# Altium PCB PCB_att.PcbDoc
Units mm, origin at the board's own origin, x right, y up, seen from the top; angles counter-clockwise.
Board outline 120.02 x 50 mm, 2 copper layers (Top Layer, Bottom Layer); 35 components, 64 nets, 213 pads, 26 vias.
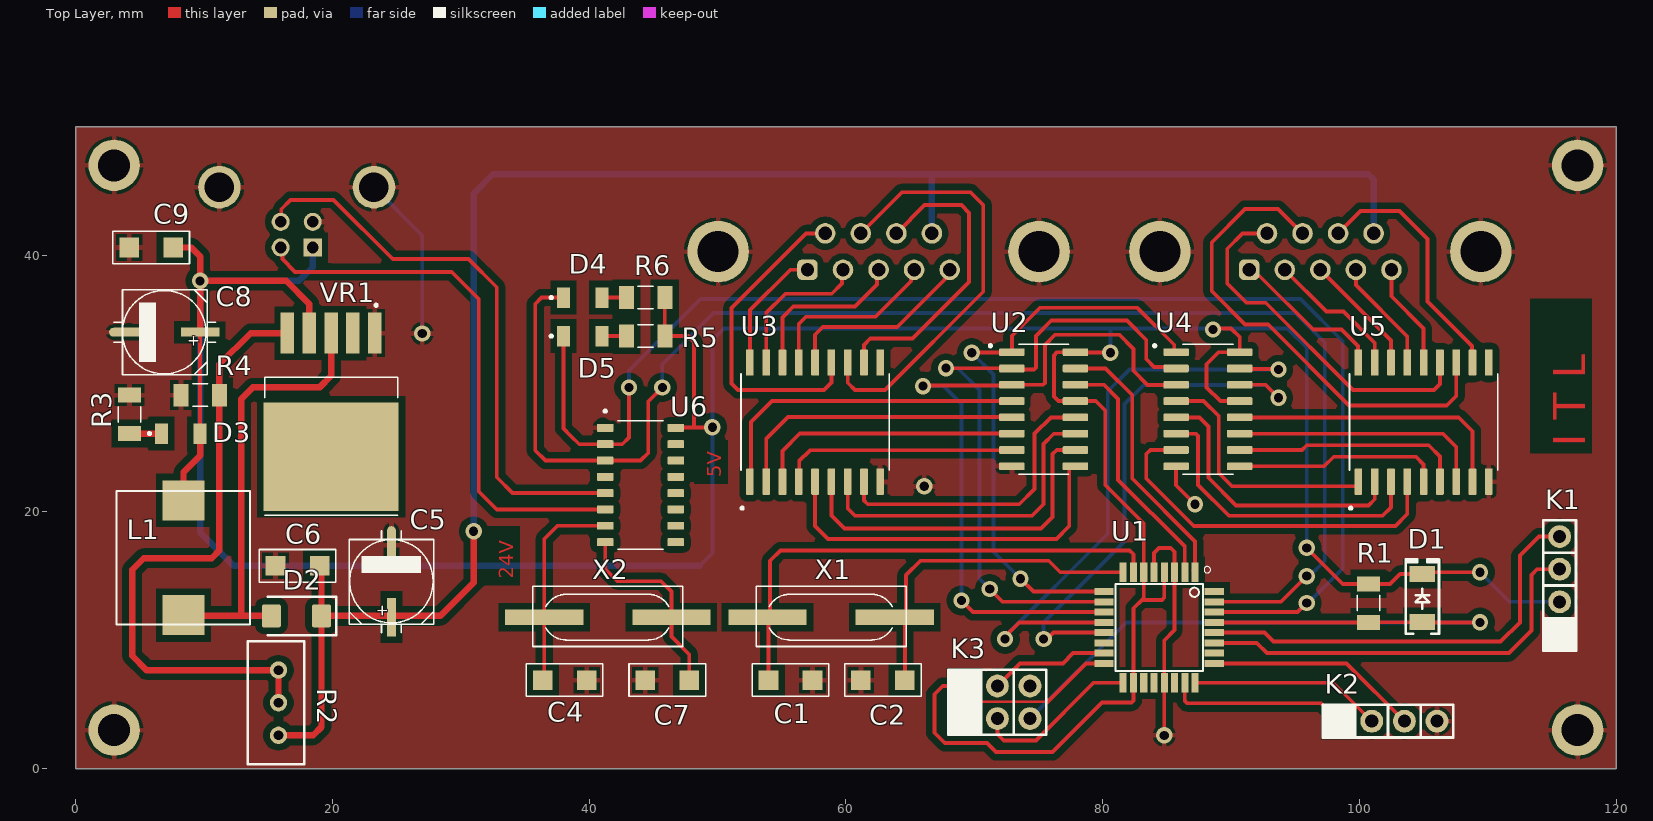
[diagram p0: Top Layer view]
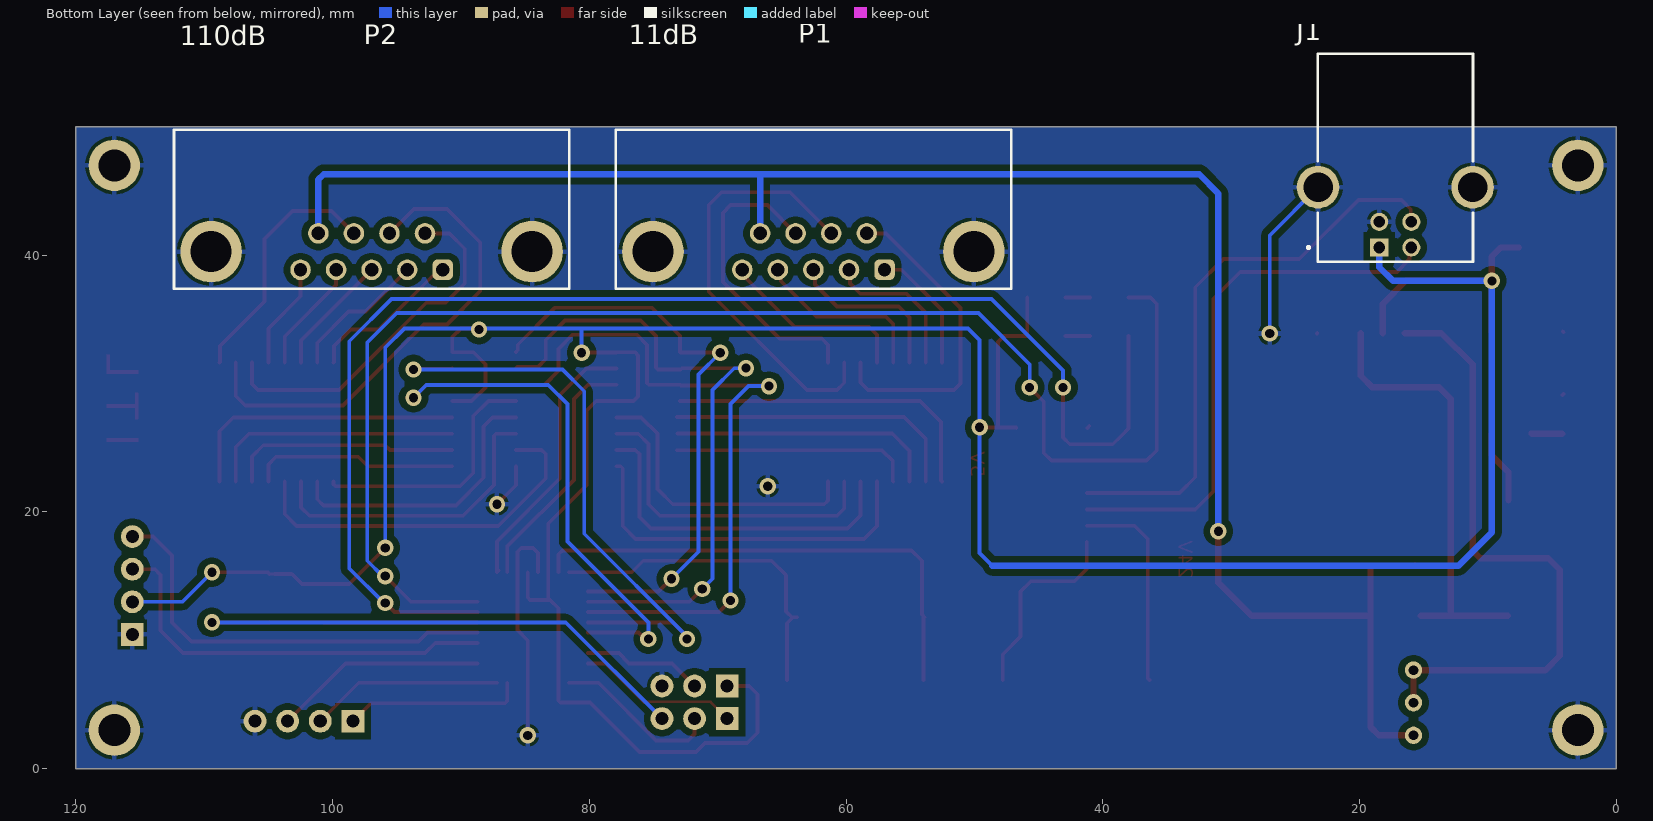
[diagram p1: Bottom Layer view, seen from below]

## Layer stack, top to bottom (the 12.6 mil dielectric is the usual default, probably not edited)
Top Solder: solder mask 0.0102, Solder Resist, Dk 3.5
Top Layer: signal copper 0.0356
Dielectric 1: dielectric 0.32, FR-4, Dk 4.8
Bottom Layer: signal copper 0.0356
Bottom Solder: solder mask 0.0102, Solder Resist, Dk 3.5

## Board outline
0,0 120.015,0 120.015,50 0,50

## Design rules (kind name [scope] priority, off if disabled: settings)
Clearance [All] p1: gap=0.5 ignorepadtopadclearanceinfootprint=FALSE
PolygonConnect [All] p1: connectstyle=Relief reliefconductorwidth=0.4 reliefentries=4 polygonreliefangle="90 Angle" airgapwidth=0.254
RoomDefinition Sch_att [InComponentClass('Sch_att')] p1: confinementstyle=ConfineIn formatcopy=TRUE lockcomponents=FALSE outline 121.2,1.4 140,1.4 140,35.6 121.2,35.6
RoutingVias [All] p1: holewidth=0.711 width=1.27 viastyle="Through Hole" minholewidth=0.711 minwidth=1.27 maxholewidth=0.711 maxwidth=1.27
SolderMaskExpansion [All] p1: expansion=0.102 istentingtop=FALSE
Width [All] p1: maxlimit=0.254 minlimit=0.254 preferedwidth=0.254
30 further rules are at their usual default settings.

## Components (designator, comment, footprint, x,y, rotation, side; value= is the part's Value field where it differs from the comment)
C1 "12pF" 1206C-GENERIC 57.4,6.9 r180 top
C2 "12pF" 1206C-GENERIC 61.171,6.9 r0 top
C4 "22pF" 1206C-GENERIC 39.8,6.9 r180 top
C5 "100u,35V" PANACAP-D-GENERIC 24.6,14.6 r90 top
C6 "50n" 1206C-GENERIC 15.571,15.8 r0 top
C7 "22pF" 1206C-GENERIC 44.371,6.9 r0 top
C8 "100u,35V" PANACAP-D-GENERIC 6.9,34 r180 top
C9 "50n" 1206C-GENERIC 4.171,40.6 r0 top
D1 "BAS83-GS08" "SOD-80 MiniMELF" 104.9,13.3 r90 top
D2 "Schottky-Diode" DO-214AC_SMA 17.2,11.9 r180 top
D3 "Red, 2V, 70°" WL-SMCW_1206_150120xx87000 8.2,26.1 r0 top
D4 "Blue, 3.2V, 70°" WL-SMCW_1206_150120xx87000 39.5,33.7 r0 top
D5 "Blue, 3.2V, 70°" WL-SMCW_1206_150120xx87000 39.5,36.7 r0 top
J1 "USB-B-S-X-X-TH" SAMTEC_USB-B-S-X-X-TH 17.22,45.3 r0 bottom
K1 "HEADER-1X4 display" HEADER-1X4 115.6,10.46 r180 top
K2 "HEADER-1X4 encoder" HEADER-1X4 98.42,3.7 r90 top
K3 "HEADER-2X3" HEADER-2X3 69.26,3.9 r90 top
L1 "470" IHLP4040DZER220M5A 8.4,16.429 r270 top
P1 "11dB" 618009231221 62.545,43.58 r0 bottom
P2 "110dB" 618009231221 96.955,43.58 r0 bottom
R1 "10k" RESC3216X75N 100.7,12.9 r270 top
R2 "10k" "BOURNS TRIMPOT 3296W" 15.8,5.14 r270 top value="100 Ohms"
R3 "5k" RESC3216X75N 4.2,27.6 r270 top
R4 "330" RESC3216X75N 9.7,29.1 r0 top
R5 "5k" RESC3216X75N 44.4,33.7 r180 top
R6 "5k" RESC3216X75N 44.4,36.7 r180 top
U1 "ATMEGA328-AU" QFP80P900X900X120-32N 84.4,11 r270 top
U2 "SN74HC259DT" SOIC127P600X175-16N 75.4,28 r0 top
U3 "ULN2803ADW" SOIC127P1030X265-18N 57.6,27 r90 top
U4 "SN74HC259DT" SOIC127P600X175-16N 88.2,28 r0 top
U5 "ULN2803ADW" SOIC127P1030X265-18N 105,27 r90 top
U6 "CH340G" SOIC127P600X180-16N 44,22.1 r0 top
VR1 "XL6009" DPAK170P1435X465-6N 19.9,27.8 r270 top
X1 "16MHz" XTAL-RU49/4 53.894,11.8 r0 top
X2 "12MHz" XTAL-RU49/4 36.5,11.8 r0 top

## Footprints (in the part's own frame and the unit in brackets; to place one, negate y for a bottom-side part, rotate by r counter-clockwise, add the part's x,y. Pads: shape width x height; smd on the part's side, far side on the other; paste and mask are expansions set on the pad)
1206C-GENERIC [mil]
  rect 60x60 smd: 1(0,0) 2(135,0)
  silkscreen extent -50,-50 185,50, body extent -8,-29 147,29, height 46
618009231221 [mm] "9 pins, right angled, 8.08mm, with hex screw"
  rrect50% 1.6x1.6 hole 1.04: 1(-5.54,4.72)
  round 1.6 hole 1.04: 2(-2.77,4.72) 3(0,4.72) 4(2.77,4.72) 5(5.54,4.72) 6(-4.155,1.88) 7(-1.385,1.88) 8(1.385,1.88) 9(4.155,1.88)
  round 4.8 hole 3.2: M1(-12.5,3.3) M2(12.5,3.3)
  silkscreen extent -15.4,-6.2 15.4,6.2, body extent -15.4,-12.2 15.4,6.2, height 12.57
"BOURNS TRIMPOT 3296W" [mm] "3296 - 3/8 ? Square Trimpot® Trimming Potentiometer"
  round 1.35 hole 0.75: 1(-2.54,0) 2(0,0) 3(2.54,0)
  silkscreen extent -4.8,-2.4 4.8,2, body extent -4.76,-2.41 4.76,2.41, height 11.56
DO-214AC_SMA [mm]
  rrect25% 1.5x1.8 smd: A(1.95,0) K(-1.95,0)
  silkscreen extent -3.1,-1.5 2.25,1.5, body extent -2.53,-1.35 2.52,1.35, height 2.17
DPAK170P1435X465-6N [mm]
  rect 3.21x1.05 smd: 1(-6.13,3.4) 2(-6.13,1.7) 3(-6.13,0) 4(-6.13,-1.7) 5(-6.13,-3.4)
  rect 8.46x10.53 smd paste-6: 6(3.5,0)
  silkscreen extent -8.4,-5.18 8.05,5.18, body extent -7.17,-5.08 7.17,5.08, height 4.65
HEADER-1X4 [mil]
  rect 70x70 hole 40: 1(0,0)
  round 70 hole 40: 2(0,-100) 3(0,-200) 4(0,-300)
  silkscreen extent -51,-350 50,50, body extent -50,-350 50,50, height 470
HEADER-2X3 [mil]
  rect 70x70 hole 40: 1(0,0) 2(100,0)
  round 70 hole 40: 3(0,-100) 4(100,-100) 5(0,-200) 6(100,-200)
  silkscreen extent -50,-250 150,50, body extent -50,-250 150,50, height 470
IHLP4040DZER220M5A [mm]
  rect 3.124x3.251 smd: 1(-4.47,0) 2(4.471,0)
  silkscreen extent -5.2,-5.2 5.2,5.2
PANACAP-D-GENERIC [mm]
  rect 3x0.7 smd: +(-2.794,0)
  oval 3x0.7 smd: -(2.794,0)
  silkscreen extent -4,-3.3 3.92,3.3, body extent -3.5,-3.3 3.5,3.3, height 5.4
QFP80P900X900X120-32N [mm]
  rect 1.5x0.55 smd: 1(-4.3,2.8) 2(-4.3,2) 3(-4.3,1.2) 4(-4.3,0.4) 5(-4.3,-0.4) 6(-4.3,-1.2) 7(-4.3,-2) 8(-4.3,-2.8) 17(4.3,-2.8) 18(4.3,-2) 19(4.3,-1.2) 20(4.3,-0.4) 21(4.3,0.4) 22(4.3,1.2) 23(4.3,2) 24(4.3,2.8)
  rect 0.55x1.5 smd: 9(-2.8,-4.3) 10(-2,-4.3) 11(-1.2,-4.3) 12(-0.4,-4.3) 13(0.4,-4.3) 14(1.2,-4.3) 15(2,-4.3) 16(2.8,-4.3) 25(2.8,4.3) 26(2,4.3) 27(1.2,4.3) 28(0.4,4.3) 29(-0.4,4.3) 30(-1.2,4.3) 31(-2,4.3) 32(-2.8,4.3)
  silkscreen extent -4.75,-3.4 3.4,4, body extent -4.5,-4.5 4.5,4.5, height 0.53
RESC3216X75N [mm]
  rect 1.17x1.77 smd: 1(-1.494,0) 2(1.494,0)
  silkscreen extent -0.59,-0.88 0.59,0.88
SAMTEC_USB-B-S-X-X-TH [mm]
  rect 1.408x1.408 / inner round 1.408 / far side rect 1.408x1.408 hole 0.9: 1(1.25,4.7)
  round 1.408 hole 0.9: 2(-1.25,4.7) 3(-1.25,2.7) 4(1.25,2.7)
  round 3.316 hole 2.3: S1(-6.02,0) S2(6.02,0)
  silkscreen extent -6.05,-10.4 6.85,5.8
"SOD-80 MiniMELF" [mm] "Molded Diode, 2-Leads, Body 3.40x1.50mm, IPC Medium Density"
  rect 1.25x2 smd: 1(-1.875,0) 2(1.875,0)
  silkscreen extent -2.8,-1.3 2.99,1.3, body extent -1.7,-0.75 1.7,0.75, height 1.5
SOIC127P600X175-16N [mm]
  rrect25% 1.97x0.6 smd: 1(-2.475,4.445) 2(-2.475,3.175) 3(-2.475,1.905) 4(-2.475,0.635) 5(-2.475,-0.635) 6(-2.475,-1.905) 7(-2.475,-3.175) 8(-2.475,-4.445) 9(2.475,-4.445) 10(2.475,-3.175) 11(2.475,-1.905) 12(2.475,-0.635) 13(2.475,0.635) 14(2.475,1.905) 15(2.475,3.175) 16(2.475,4.445)
  silkscreen extent -4.24,-5.06 1.95,5.06
SOIC127P600X180-16N [mm]
  rrect25% 1.31x0.62 smd: 1(-2.75,4.445) 2(-2.75,3.175) 3(-2.75,1.905) 4(-2.75,0.635) 5(-2.75,-0.635) 6(-2.75,-1.905) 7(-2.75,-3.175) 8(-2.75,-4.445) 9(2.75,-4.445) 10(2.75,-3.175) 11(2.75,-1.905) 12(2.75,-0.635) 13(2.75,0.635) 14(2.75,1.905) 15(2.75,3.175) 16(2.75,4.445)
  silkscreen extent -2.85,-5 1.78,5.85, body extent -3,-5 3,5, height 1.8
SOIC127P1030X265-18N [mm]
  rrect25% 2.06x0.6 smd: 1(-4.64,5.08) 2(-4.64,3.81) 3(-4.64,2.54) 4(-4.64,1.27) 5(-4.64,0) 6(-4.64,-1.27) 7(-4.64,-2.54) 8(-4.64,-3.81) 9(-4.64,-5.08) 10(4.64,-5.08) 11(4.64,-3.81) 12(4.64,-2.54) 13(4.64,-1.27) 14(4.64,0) 15(4.64,1.27) 16(4.64,2.54) 17(4.64,3.81) 18(4.64,5.08)
  silkscreen extent -6.8,-5.78 3.75,5.78, body extent -5.15,-5.77 5.15,5.77, height 2.65
WL-SMCW_1206_150120xx87000 [mm] "LED, SMT, 2-leads, body 3.20x1.60mm"
  rect 1x1.6 smd: 1(-1.5,0) 2(1.5,0)
  silkscreen extent -2.55,-0.1 -2.35,0.1, body extent -1.6,-0.8 1.6,0.8, height 1.1
XTAL-RU49/4 [mil]
  rect 240x47.24 smd: 1(0,0) 2(390,0)
  silkscreen extent -35,-90 425,95, body extent -78,-90 468,95, height 120

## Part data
C1 C2 C4 C6 C7 C9: library part 1206C-10U-35V-X7R, "GENERIC CAPACITOR NON POLARISED 1206", Manufacturer="Taiyo Yuden", Manufacturer Part Number=GMK316F106ZL-T, Supplier Part Number 1=587-1352-2-ND
C5 C8: library part PANACAP-100UF-16V-FK, "GENERIC CAPACITOR POLARISED", Supplier Part Number 1=PCE3783TR-ND
D1: "DIODE SCHOTTKY 60V 30MA SOD80", Capacitance @ Vr, F="1.6pF @ 1V, 1MHz", Current - Average Rectified (Io)="30mA (DC)", Current - Reverse Leakage @ Vr="200nA @ 60V", Manufacturer="Vishay Semiconductor Diodes Division", Operating Temperature - Junction="125°C (Max)", Package / Case="DO-213AC, MINI-MELF, SOD-80", Supplier Device Package="SOD-80 MiniMELF", Supplier Part Number 1=BAS83-GS08GICT-ND, Voltage - DC Reverse (Vr) (Max)=60V, Voltage - Forward (Vf) (Max) @ If="1V @ 15mA"
D3: library part 150120RS87000, "WL-SMCW Mono-color Chip LED Waterclear, size 1206, Red, 2V, 70°", Case/Size Code=1206, Emitting Color=Red, Forward Voltage=2V, Manufacturer="Wurth Elektronik", Operating Temperature Max=85°C, Operating Temperature Min=-40°C
D4 D5: library part 150120BS87000, "WL-SMCW Mono-color Chip LED Waterclear, size 1206, Blue, 3.2V, 70°", Case/Size Code=1206, Emitting Color=Blue, Forward Voltage=3.2V, Manufacturer="Wurth Elektronik", Operating Temperature Max=85°C, Operating Temperature Min=-40°C
J1: "USB-B (USB TYPE-B) USB 2.0 Receptacle Connector 4 Position Through Hole, Right Angle", Package=None
K1 K2: library part HEADER-1X4, Supplier Part Number 1=S1011E-36-ND
L1: library part IHLP4040DZER220M5A, "22 ÂµH Shielded Molded Inductor 4.1 A 75.44mOhm Max Nonstandard", Package="Nonstandard Vishay Dale"
P1 P2: library part 618009231221, "WR-DSUB 8.08mm Male PCB Connector with Hex Screw, Angled, 9p", Contact Resistance=30mOhm, Manufacturer="Wurth Elektronik", Operating Temperature Max=105°C, Operating Temperature Min=-55°C, Rated Current=3A, Withstanding Voltage=100VAC, Working Voltage=125VAC
R1: library part CR1206-FX-4701ELF, "RES 10K OHM 1/4W 1% 1206 SMD", Package=None
R2: library part 3296W-1-101RLF, "TRIMMER 100 OHM 0.5W PC PIN TOP", Manufacturer="Bourns Inc.", Power (Watts)="0.5W, 1/2W", Resistance="100 Ohms", Resistive Material=Cermet, Supplier Part Number 1=118-3296W-1-101RLFCT-ND, Temperature Coefficient=±100ppm/°C, Tolerance=±10%
R3 R4 R5 R6: library part CR1206-FX-4701ELF, "RES 5K OHM 1/4W 1% 1206 SMD", Package=None
U1: "AVR AVRÂ® ATmega Microcontroller IC 8-Bit 20MHz 32KB (16K x 16) FLASH 32-TQFP (7x7)", Package="TQFP-32 Microchip"
U2 U4: Package=None
U3 U5: "50-V, 8-ch darlington array", Package="SOIC-18 Texas Instruments"
U6: "USB Interface Integrated Circuit", Package=None
VR1: "The XL6009 regulator is a wide input range, current mode, DC/DC converter which is capable of generating either positive or negative output voltages.", Package="TO-263-5L XLSEMI"
X1 X2: library part CRYSTAL-GENERIC, "GENERIC CRYSTAL"

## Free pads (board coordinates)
  round 4 hole 2.5: ""(3,3) ""(3,47) ""(117,3) ""(117,47)

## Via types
v1: diameter 1.27, hole 0.711, Top Layer to Bottom Layer, 26 vias

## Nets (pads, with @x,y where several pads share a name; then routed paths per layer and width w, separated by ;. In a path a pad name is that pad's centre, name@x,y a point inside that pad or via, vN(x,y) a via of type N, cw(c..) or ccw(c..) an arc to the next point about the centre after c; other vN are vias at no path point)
1-1C: P1.1 U3.18 | length 9.9
  Top Layer w0.3: U3.18 52.52,35.72 55.66,38.86 P1.1
1-2C: P1.2 U3.17 | length 11.8
  Top Layer w0.3: U3.17 53.79,35.49 55.3,37 58.9,37 59.686,37.786 59.686,38.771 P1.2
1-3C: P1.3 U3.16 | length 13.1
  Top Layer w0.3: U3.16 55.06,35.16 55.9,36 60.7,36 62.419,37.719 62.419,38.734 P1.3
1-4C: P1.4 U3.15 | length 14.1
  Top Layer w0.3: U3.15 56.33,34.63 56.9,35.2 62.3,35.2 65.066,37.966 65.066,38.611 P1.4
1-5C: P1.5 U3.14 | length 15
  Top Layer w0.3: U3.14 57.6,33.8 58.2,34.4 64,34.4 67.689,38.089 67.689,38.112 68.085,38.508 P1.5
1-6C: P1.6 U3.13 | length 25.4
  Top Layer w0.3: P1.6 56.9,41.7 51.1,35.9 51.1,30 51.6,29.5 58.3,29.5 58.87,30.07 U3.13
1-7C: P1.7 U3.12 | length 33.6
  Top Layer w0.3: U3.12 60.14,30.06 60.7,29.5 63.049,29.5 70.7,37.151 70.7,43.9 69.7,44.9 64.36,44.9 P1.7
1-8C: P1.8 U3.11 | length 23.8
  Top Layer w0.3: U3.11 61.41,33.01 61.9,33.5 65.2,33.5 69.6,37.9 69.6,43.3 69,43.9 66.13,43.9 P1.8
2-1C: P2.1 U5.18 | length 12.2
  Top Layer w0.3: P2.1 91.911,38.364 92.236,38.364 96.4,34.2 98.6,34.2 99.879,32.921 99.879,31.681 U5.18
2-2C: P2.2 U5.17 | length 10.9
  Top Layer w0.3: P2.2 97.445,35.6 98.763,35.6 101.19,33.173 U5.17
2-3C: P2.3 U5.16 | length 9.5
  Top Layer w0.3: P2.3 102.46,33.355 U5.16
2-4C: P2.4 U5.15 | length 8.9
  Top Layer w0.3: P2.4 99.725,37.675 103.73,33.67 U5.15
2-5C: P2.5 U5.14 | length 8.3
  Top Layer w0.3: P2.5 102.495,36.805 105,34.3 U5.14
2-6C: P2.6 U5.13 | length 28.2
  Top Layer w0.3: P2.6 90.9,41.7 89.7,40.5 89.7,37.8 91.2,36.3 92.7,36.3 99.5,29.5 105.8,29.5 106.27,29.97 U5.13
2-7C: P2.7 U5.12 | length 38.4
  Top Layer w0.3: P2.7 93.67,43.6 91.1,43.6 88.5,41 88.5,37.2 91.1,34.6 92.9,34.6 99.2,28.3 106.8,28.3 107.54,29.04 U5.12
2-8C: P2.8 U5.11 | length 19.7
  Top Layer w0.3: P2.8 100.084,43.444 103.119,43.444 105.31,41.254 105.31,36.39 108.774,32.926 108.774,31.676 U5.11
24V: C5.+ C6.2 D2.K P1.9 P2.9 R2.3 | length 139.3
  Top Layer w0.3: C6.2 C6.2@19.15,15.65 ; C5.+@24.506,11.9 C5.+ C5.+@24.694,11.9
  Top Layer w0.5: R2.3 18.5,2.6 19.15,3.25 D2.K ; C6.2@19.15,15.65 D2.K ; C5.+@24.506,11.9 D2.K ; C5.+@24.694,11.9 28.4,11.9 31,14.5 v1(31,18.5)
  Bottom Layer w0.3: 66.7,46.2 66.8,46.3 66.7,46.3
  Bottom Layer w0.5: v1(31,18.5) 31,44.8 32.5,46.3 66.7,46.3 ; P1.9 66.7,46.2 ; 66.8,46.3 100.7,46.3 101.11,45.89 P2.9
CLR1: U1.1 U2.15 | length 21.2
  Top Layer w0.3: U2.15 80.225,31.175 82.3,29.1 82.3,22.6 87.2,17.7 U1.1@87.2,15.444 ; U1.1@87.056,15.444 U1.1
CLR2: U1.12 U4.15 | length 47.6
  Top Layer w0.3: v1@72.4,10.3 73.5,11.4 U1.12 ; U4.15 90.713,31.137 93.663,31.137 v1(93.7,31.1)
  Bottom Layer w0.3: v1@72.4,10.3 80.4,18.3 80.4,29.4 82.1,31.1 v1(93.7,31.1)
  other v1: 72.4,10.1
D+: J1.3 U6.5 | length 44.7
  Top Layer w0.3: J1.3 16.021,42.651 16.021,43.578 16.743,44.3 20.1,44.3 24.7,39.7 30.6,39.7 32.8,37.5 32.8,22.7 34.035,21.465 U6.5
D-: J1.2 U6.6 | length 43
  Top Layer w0.3: J1.2 16.101,40.469 16.101,39.699 17.1,38.7 29.3,38.7 31.405,36.595 31.405,21.595 32.805,20.195 U6.6
EN1: U1.2 U2.14 | length 19.4
  Top Layer w0.3: U2.14 80.095,29.905 81.2,28.8 81.2,22.5 86.4,17.3 U1.2
EN2: U1.13 U4.14 | length 42.8
  Top Layer w0.3: v1(75.4,10.1) 75.675,10.1 76.175,10.6 U1.13 ; U4.14 92.695,29.905 v1(93.7,28.9) v1@94.2,28.9
  Bottom Layer w0.3: v1(75.4,10.1) 75.4,11.4 81.7,17.7 81.7,28.4 83.2,29.9 92.7,29.9 v1(93.7,28.9)
enc1: K2.1 U1.23 | length 14.1
  Top Layer w0.3: U1.23 86.4,5.276 86.576,5.1 97.02,5.1 K2.1
enc2: K2.2 U1.24 | length 15
  Top Layer w0.3: U1.24 97.96,6.7 K2.2
enc3: K2.3 U1.25 | length 16.7
  Top Layer w0.3: U1.25 99,8.2 K2.3
GND: C1.1 C2.1 C4.1 C5.- C6.1 C7.1 C8.- C9.1 J1.4 J1.S1 J1.S2 K1.1 K2.4 K3.6 P1.M1 P1.M2 P2.M1 P2.M2 pad. R3.1 R4.1 U1.3 U1.5 U1.21 U2.8 U3.9 U4.8 U5.9 U6.1 VR1.1 | length 37.6
  Top Layer w0.3: pad.@3,3 pad.@3,3.167 ; pad.@3,46.833 3,47 pad.@4.014,47 ; R3.1@4.106,29.188 R3.1 R3.1@4.206,29.1 ; C8.- C8.-@4.171,34.065 ; C6.1 C6.1@15.694,15.923 ; VR1.1 VR1.1@23.33,33.9 ; U6.1@41.055,26.694 U6.1@41.204,26.545 ; U1.5 84,16.8 84.4,17.2 85.3,17.2 85.6,16.9 U1.3 85.6,10.8 84.8,10 U1.21 v1(84.8,2.6) ; U4.8 85.725,22.075 v1(87.2,20.6) ; pad.@115.986,47 pad.@117,47
  Bottom Layer w0.3: J1.S2 27,41.54 v1(27,33.9)
  other v1: 66.1,22
MISO: K3.1 U1.16 | length 12.6
  Top Layer w0.2: K3.1 70.56,5.2 75.7,5.2
  Top Layer w0.3: 75.7,5.2 78.7,8.2 U1.16
MOSI: K3.4 U1.15 | length 9.4
  Top Layer w0.3: K3.4 73.56,8.2 76.9,8.2 77.7,9 U1.15
NetC1_2: C1.2 U1.7 X1.1 | length 39.5
  Top Layer w0.3: X1.1 54.1,12.006 54.1,16.2 54.9,17 82.1,17 82.4,16.7 U1.7 ; C1.2 X1.1@53.971,11.8
NetC2_2: C2.2 U1.8 X1.2 | length 26.7
  Top Layer w0.3: X1.2 X1.2@64.127,11.8 ; C2.2 64.6,11.327 X1.2@64.127,11.8 ; U1.8 78.1,15.3 76.7,15.3 75.8,16.2 65.8,16.2 64.674,15.074 64.674,12.25 64.224,11.8 X1.2@64.127,11.8
NetC4_2: C4.2 U6.7 X2.1 | length 16.2
  Top Layer w0.3: C4.2 36.5,7.029 X2.1 36.5,17.9 37.525,18.925 U6.7
NetC7_2: C7.2 U6.8 X2.2 | length 15.5
  Top Layer w0.3: U6.8 41.25,15.55 42.2,14.6 45.6,14.6 46.406,13.794 X2.2 46.406,10.294 47.8,8.9 C7.2
NetD2_A: D2.A L1.2 VR1.3 | length 34.8
  Top Layer w0.3: L1.2 L1.2@8.459,11.9
  Top Layer w0.5: L1.2@8.459,11.9 12.9,11.9 ; D2.A 12.9,11.9 ; VR1.3 19.9,30.6 19,29.7 13.8,29.7 12.9,28.8 12.9,11.9
NetD3_1: D3.1 R3.2 | length 2.5
  Top Layer w0.3: D3.1@6.606,26.106 D3.1@6.7,26.2
  Top Layer w0.5: R3.2 D3.1@6.606,26.106
NetD4_2: D4.2 R5.2 | length 1.9
  Top Layer w0.3: D4.2 R5.2
NetD5_2: D5.2 R6.2 | length 1.9
  Top Layer w0.3: D5.2 R6.2
NetR2_1: R2.1 R2.2 R4.2 VR1.5 | length 49.3
  Top Layer w0.5: R2.2 R2.1 5.52,7.68 4.4,8.8 4.4,15.5 5.3,16.4 10.6,16.4 11.194,16.994 R4.2 11.194,31.494 13.63,33.93 VR1.5
NetU2_4: U2.4 U3.1 | length 25.7
  Top Layer w0.3: U3.1 52.6,22.44 52.6,27 54.235,28.635 U2.4
NetU2_5: U2.5 U3.2 | length 23.4
  Top Layer w0.3: U3.2 53.79,25.69 55.5,27.4 U2.5@73.17,27.4
NetU2_6: U2.6 U3.3 | length 21.1
  Top Layer w0.3: U3.3 55.06,24.76 56.4,26.1 U2.6@73.155,26.1
NetU2_7: U2.7 U3.4 | length 18.8
  Top Layer w0.3: U3.4 56.36,22.39 56.36,23.96 57.2,24.8 U2.7@73.168,24.8
NetU2_9: U2.9 U3.5 | length 29.1
  Top Layer w0.3: U3.5 57.6,18.9 58.6,17.9 76.4,17.9 77.4,18.9 77.4,23.405 77.55,23.555 U2.9
NetU2_10: U2.10 U3.6 | length 27.5
  Top Layer w0.3: U3.6 58.87,19.73 59.9,18.7 75.2,18.7 76.1,19.6 76.1,24.5 76.425,24.825 U2.10
NetU2_11: U2.11 U3.7 | length 25.5
  Top Layer w0.3: U3.7 60.14,20.26 60.7,19.7 74.5,19.7 75.4,20.6 75.4,25.3 76.195,26.095 U2.11
NetU2_12: U2.12 U3.8 | length 23.4
  Top Layer w0.3: U3.8 61.41,20.89 61.7,20.6 73.5,20.6 74.7,21.8 74.7,26.1 75.965,27.365 U2.12
NetU4_4: U4.4 U5.1 | length 19.8
  Top Layer w0.3: U4.4 87.865,28.635 89.04,27.46 89.04,23.03 90.07,22 99.77,22 99.92,22.15 U5.1
NetU4_5: U4.5 U5.2 | length 22.2
  Top Layer w0.3: U4.5 87.535,27.365 88.24,26.66 88.24,22.66 90.4,20.5 100.7,20.5 101.19,20.99 U5.2
NetU4_6: U4.6 U5.3 | length 23.9
  Top Layer w0.3: U4.6 87.264,26.095 87.44,25.919 87.44,22.097 89.837,19.7 101.8,19.7 102.46,20.36 U5.3
NetU4_7: U4.7 U5.4 | length 29.1
  Top Layer w0.3: U4.7 83.725,24.825 83.4,24.5 83.4,22.6 87.1,18.9 102.8,18.9 103.73,19.83 U5.4
NetU4_9: U4.9 U5.5 | length 16.2
  Top Layer w0.3: U4.9 97.255,23.555 98,24.3 104.4,24.3 105,23.7 U5.5
NetU4_10: U4.10 U5.6 | length 18.1
  Top Layer w0.3: U4.10 95.525,24.825 95.9,25.2 105.4,25.2 106.27,24.33 U5.6
NetU4_11: U4.11 U5.7 | length 20
  Top Layer w0.3: U4.11 106.505,26.095 107.54,25.06 U5.7
NetU4_12: U4.12 U5.8 | length 22.5
  Top Layer w0.3: U4.12 107.735,27.365 108.81,26.29 U5.8
RST: D1.1 K3.5 R1.2 U1.29 | length 58.5
  Top Layer w0.3: U1.29 R1.2@100.7,11.4 ; R1.2 104.881,11.406 D1.1 104.925,11.4 v1@109.2,11.4
  Bottom Layer w0.3: K3.5 81.84,11.4 v1@109.2,11.4
  other v1: 109.4,11.4
RXD: D5.1 U1.31 U6.3 | length 111.7
  Top Layer w0.3: D5.1 36.3,36.7 35.8,36.2 35.8,24.8 36.595,24.005 U6.3 44.005,24.005 44.6,24.6 44.6,28.6 v1(45.7,29.7) ; U1.31 93.9,13 v1(95.9,15)
  Bottom Layer w0.3: v1(45.7,29.7) 45.7,31.5 49.7,35.5 95,35.5 97.3,33.2 97.3,16.2 96.1,15 v1(95.9,15)
S0: U1.9 U2.1 U4.1 | length 45.9
  Top Layer w0.3: v1(69.8,32.4) 69.823,32.423 72.902,32.423 U2.1 72.925,33.725 75.1,35.9 82.7,35.9 85.581,33.019 85.581,32.595 85.725,32.451 U4.1 ; v1(73.6,14.8) 74.6,13.8 U1.9
  Bottom Layer w0.3: v1(69.8,32.4) 71.5,30.7 71.5,16.9 v1(73.6,14.8)
S1: U1.10 U2.2 U4.2 | length 51.8
  Top Layer w0.3: v1(67.8,31.2) 67.812,31.188 72.806,31.188 72.893,31.1 74.651,31.1 74.8,31.249 74.8,33.7 76,34.9 81.9,34.9 83.4,33.4 83.4,31.9 84,31.3 85.6,31.3 U4.2 ; v1(71.2,14) 72.2,13 U1.10
  Bottom Layer w0.3: v1(67.8,31.2) 67.809,31.191 68.709,31.191 70.4,29.5 70.4,14.8 v1(71.2,14)
S2: U1.11 U2.3 U4.3 | length 56.1
  Top Layer w0.3: v1(66,29.8) 66.053,29.853 72.872,29.853 U2.3 75.351,29.905 75.5,30.054 75.5,33 76.3,33.8 81.3,33.8 82.4,32.7 82.4,31 83.5,29.9 85.72,29.9 U4.3 ; v1(69,13.1) 69.9,12.2 U1.11
  Bottom Layer w0.3: v1(66,29.8) 67.6,29.8 69,28.4 v1(69,13.1)
SCK: K3.3 U1.17 | length 13.1
  Top Layer w0.3: K3.3 71.8,2.7 72.3,2.2 74.8,2.2 79.3,6.7 U1.17
SCL: K1.4 U1.28 | length 33.6
  Top Layer w0.3: U1.28 92.6,10.6 93.3,9.9 111,9.9 112.5,11.4 112.5,16.6 113.98,18.08 K1.4
SDA: K1.3 U1.27 | length 32.5
  Top Layer w0.3: U1.27 92,9.8 92.8,9 111.64,9 113.4,10.76 113.4,15.1 113.84,15.54 K1.3
TXD: D4.1 U1.30 U6.2 | length 106.6
  Top Layer w0.3: D4.1 38,26.5 38.6,25.9 39.225,25.275 U6.2 42.575,25.275 43.1,25.8 v1(43.1,29.7) ; U1.30 95.166,12.2 95.866,12.9 v1@96,12.9
  Bottom Layer w0.3: v1(43.1,29.7) 43.1,31.016 48.684,36.6 95.4,36.6 98.7,33.3 98.7,15.6 v1@96,12.9
  other v1: 95.9,12.9
VCC: C8.+ C9.2 D1.2 D3.2 J1.1 K1.2 K3.2 L1.1 R1.1 R5.1 R6.1 U1.4 U1.6 U1.18 U2.13 U2.16 U4.13 U4.16 U6.16 VR1.4 | length 298.6
  Top Layer w0.254: D1.2@104.525,15.175 D1.2
  Top Layer w0.3: D3.2@9.694,26.206 C8.+ C8.+@9.7,34.006 ; R6.1 R5.1 47.7,33.7 48.175,33.225 48.175,26.572 ; U6.16 46.777,26.572 48.175,26.572 ; v1(49.6,26.6) 49.572,26.572 48.175,26.572 ; K3.2 67.54,6.44 66.9,5.8 66.9,2.8 67.7,2 71,2 71.7,1.3 76.1,1.3 79.949,5.149 82.251,5.149 82.4,5.298 U1.18 82.4,12.5 83.05,13.15 ; v1(80.6,32.4) 80.577,32.423 77.897,32.423 U2.16 76.445,32.445 76.2,32.2 76.2,29 76.565,28.635 U2.13 79.465,28.635 80.2,27.9 80.2,22.1 83.2,19.1 U1.6 83.2,13.3 83.05,13.15 ; U1.4 84.8,13.326 84.624,13.15 83.05,13.15 ; v1(88.6,34.215) 88.685,34.3 90,34.3 90.675,33.625 U4.16 89.045,32.445 88.1,31.5 88.1,29.7 89.165,28.635 U4.13 ; v1(95.9,17.2) 98.706,14.394 R1.1 102.394,14.394 103.175,15.175 D1.2@104.525,15.175 ; D1.2 105.025,15.3 v1(109.4,15.3)
  Top Layer w0.5: C9.2 9,40.6 9.7,39.9 v1(9.7,38) ; L1.1 8.4,23.1 9.7,24.4 D3.2 ; C8.+@9.7,34.006 v1(9.7,38) ; VR1.4 18.2,36.2 16.4,38 v1(9.7,38)
  Bottom Layer w0.3: 48.6,15.8 49.6,16.8 v1(49.6,26.6) 49.6,33.4 50.5,34.3 80.6,34.3 ; v1(80.6,32.4) 80.6,34.3 ; v1(88.6,34.215) 88.515,34.3 80.6,34.3 ; v1@88.6,34.3 94.4,34.3 95.9,32.8 v1(95.9,17.2) ; v1(109.4,15.3) 111.7,13 K1.2
  Bottom Layer w0.5: J1.1 18.47,39.07 17.4,38 v1(9.7,38) 9.7,18.4 12.3,15.8 48.6,15.8
pads on no net: U1.14 U1.19 U1.20 U1.22 U1.26 U1.32 U3.10 U5.10 U6.4 U6.9 U6.10 U6.11 U6.12 U6.13 U6.14 U6.15 VR1.2 VR1.6

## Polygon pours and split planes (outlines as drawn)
GND on Bottom Layer "GND_L02_P001" (solid, pour order 1): 0,0 0,50 120,50 120,0
GND on Top Layer "GND_L01_P000" (solid, pour order 0): 0,0 0,50 120,50 120,0

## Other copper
Top Layer:
  text "I T L" at 117.6,25.078 h2.5 r90
  text "5V" at 50.3,22.7 h1.1 r90
  text "24V" at 34.1,14.8 h1.1 r90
